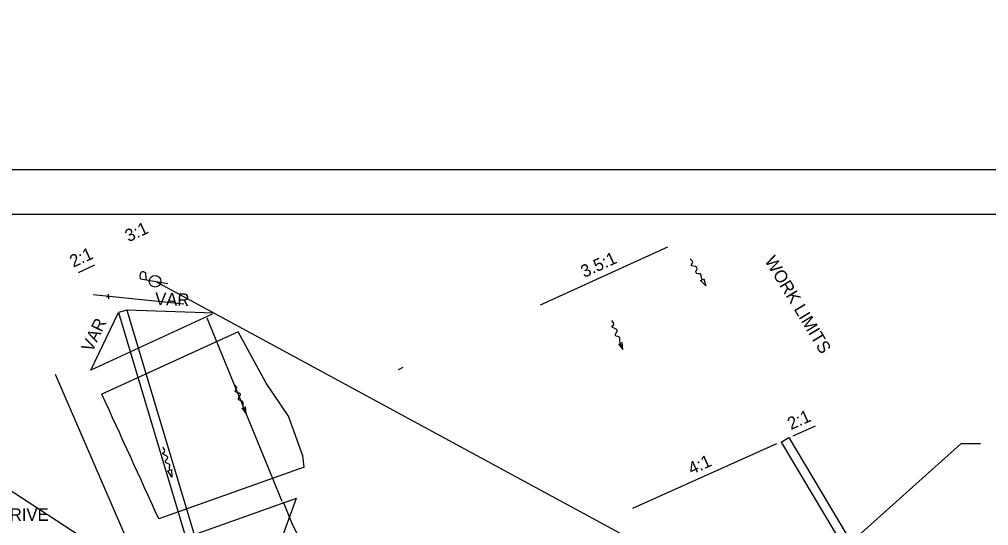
# Model space of a CAD drawing. Extents: x -1270 to 3371, y -118 to 220.
# Drawn here: x -1179.1 to -1070.2, y 76.8 to 133.7 of the extents above; entities that cross this region are included whole.
import ezdxf

# ---------------------------------------------------------------- set-up
doc = ezdxf.new("R2010")
doc.units = 0
for name, color, linetype in [('Default', 7, 'Continuous'), ('DR_X_Culvert', 7, 'Continuous'), ('GE_P_Alignment', 7, 'Continuous'), ('GE_P_Alignment_100_Distances', 7, 'Continuous'), ('GE_P_Alignment_100_Stations', 7, 'Continuous'), ('MT_P_Work_Area', 7, 'Continuous'), ('PF_P_Grade_Line', 7, 'Continuous'), ('TX_P_1', 7, 'Continuous'), ('TX_X_1', 7, 'Continuous')]:
    doc.layers.add(name, color=color, linetype=linetype)

msp = doc.modelspace()

# ---------------------------------------------------------------- linework, layer by layer
at = {"layer": 'Default'}
for p, q in [((-1120.54, 101.62), (-1106.25, 108.14)), ((-1172.47, 105.25), (-1170.63, 106.11)), ((-1165.48, 104.55), (-1165.52, 104.97)), ((-1165.48, 104.55), (-1162.43, 104)), ((-1164.83, 104.43), (-1164.88, 105.03)), ((-1164.66, 103.82), (-1164.66, 103.82)), ((-1164.66, 103.82), (-1164.66, 103.82)), ((-1164.66, 103.82), (-1164.66, 103.82)), ((-1163.85, 104.26), (-1083.18, 60.61)), ((-1163.85, 104.26), (-1163.85, 104.26)), ((-1160.63, 101.67), (-1170.81, 102.74)), ((-1169.3, 102.53), (-1168.8, 102.57)), ((-1169.03, 102.3), (-1169.07, 102.8)), ((-1169.05, 102.55), (-1169.05, 102.55)), ((-1171.08, 94.29), (-1167.97, 100.74)), ((-1157.44, 100.55), (-1171.08, 94.29)), ((-1157.2, 100.66), (-1167.01, 101.02)), ((-1158.05, 100.16), (-1149.6, 79.58)), ((-1154.52, 98.59), (-1169.82, 91.57)), ((-1166.15, 73.31), (-1175.04, 93.79)), ((-1089.69, 88), (-1092.19, 86.87)), ((-1110.19, 78.77), (-1094.01, 86.05)), ((-1147.09, 83.38), (-1163.43, 77.57)), ((-1148, 79.88), (-1162.42, 74.75)), ((-1148, 79.88), (-1156.01, 58.15))]:
    msp.add_line(p, q, dxfattribs=at)
for points in [[(-1147.09, 83.38), (-1147.24, 84.66), (-1148.87, 89.13), (-1151.38, 92.83), (-1154.52, 98.59)], [(-1149.47, 79.5), (-1148.52, 77.18), (-1145.9, 71.77), (-1143.88, 68.91), (-1143.36, 66.12), (-1142.76, 64.06), (-1140.56, 59.52), (-1140, 56.26), (-1138.98, 52.98), (-1139.13, 50.64)]]:
    msp.add_lwpolyline(points, dxfattribs=at)
msp.add_circle((-1163.85, 104.26), 0.65, dxfattribs=at)
for centre, radius, start, end in [((-1165.2, 105.01), 0.319, 3.6136, 185.8602), ((-5673.47, -1975.02), 4955.16, 24.47104, 24.64895)]:
    msp.add_arc(centre, radius, start, end, dxfattribs=at)
at = {"layer": 'DR_X_Culvert'}
msp.add_lwpolyline([(-1245.26, -103.22), (-905.26, -103.22), (-905.26, 116.78), (-1245.26, 116.78)], close=True, dxfattribs=at)
at = {"layer": 'GE_P_Alignment_100_Distances'}
for p, q in [((-1111.78, 97.25), (-1111.29, 96.58)), ((-1111.29, 96.58), (-1111.38, 97.41)), ((-1154.11, 90.06), (-1153.62, 89.39)), ((-1153.62, 89.39), (-1153.71, 90.21))]:
    msp.add_line(p, q, dxfattribs=at)
for points in [[(-1111.29, 96.58), (-1111.59, 97.36), (-1111.64, 97.7), (-1111.65, 97.92), (-1112.14, 98.18), (-1111.93, 98.78), (-1112.52, 99.15), (-1112.35, 99.34), (-1112.55, 99.85)], [(-1153.62, 89.39), (-1153.92, 90.16), (-1153.97, 90.5), (-1153.98, 90.72), (-1154.48, 90.98), (-1154.27, 91.58), (-1154.86, 91.95), (-1154.7, 92.14), (-1154.91, 92.64)]]:
    msp.add_spline(points, degree=3, dxfattribs=at)
at = {"layer": 'GE_P_Alignment_100_Stations'}
for p, q in [((-1102.57, 104.33), (-1102.2, 104.55)), ((-1102.2, 104.55), (-1101.99, 103.75)), ((-1101.99, 103.75), (-1102.57, 104.33)), ((-1162.4, 82.99), (-1161.99, 83.11)), ((-1161.96, 82.28), (-1162.4, 82.99)), ((-1161.99, 83.11), (-1161.96, 82.28))]:
    msp.add_line(p, q, dxfattribs=at)
for points in [[(-1102.39, 104.44), (-1102.4, 104.47), (-1102.5, 104.79), (-1102.55, 105.01), (-1103.08, 105.19), (-1102.97, 105.82), (-1103.61, 106.09), (-1103.47, 106.3), (-1103.75, 106.77)], [(-1162.19, 83.05), (-1162.2, 83.08), (-1162.22, 83.42), (-1162.21, 83.64), (-1162.69, 83.94), (-1162.43, 84.52), (-1162.99, 84.94), (-1162.81, 85.11), (-1162.97, 85.64)]]:
    msp.add_spline(points, degree=3, dxfattribs=at)
at = {"layer": 'MT_P_Work_Area'}
msp.add_line((-1136.01, 94.57), (-1136.55, 94.32), dxfattribs=at)
at = {"layer": 'PF_P_Grade_Line'}
for p, q in [((-1167.01, 101.02), (-1167.97, 100.74)), ((-1167.97, 100.74), (-1154.78, 56.67)), ((-1167.01, 101.02), (-1153.82, 56.95)), ((-1093.53, 86.21), (-1092.67, 86.72)), ((-1093.53, 86.21), (-1076.08, 57.03)), ((-1092.67, 86.72), (-1075.22, 57.54))]:
    msp.add_line(p, q, dxfattribs=at)
at = {"layer": 'TX_P_1'}
for p, q in [((-1261.12, 133.66), (-876.01, -117.63)), ((-1115.28, 48.52), (-1073.33, 85.99)), ((-1071.11, 85.99), (-1073.33, 85.99))]:
    msp.add_line(p, q, dxfattribs=at)
at = {"layer": 'TX_X_1'}
msp.add_lwpolyline([(-1230.26, 111.78), (-910.26, 111.78), (-910.26, -98.22), (-1230.26, -98.22)], close=True, dxfattribs=at)

# ---------------------------------------------------------------- texts
at = {"layer": 'GE_P_Alignment'}
msp.add_text('RESIDENTIAL DRIVE', height=1.4, dxfattribs=at).set_placement((-1194.32, 77.36))
at = {"layer": 'TX_P_1'}
for s, rotation, p in [('3:1', 24.8054, (-1166.83, 108.63)), ('2:1', 24.8054, (-1173.04, 105.77)), ('3.5:1', 24.5182, (-1115.64, 104.63)), ('WORK LIMITS', 301.1437, (-1095.42, 106.58)), ('VAR', 357.8847, (-1163.87, 101.61)), ('VAR', 64.2667, (-1170.93, 96.21)), ('VAR', 64.2667, (-1170.93, 96.21)), ('2:1', 24.231, (-1092.42, 87.54)), ('4:1', 24.231, (-1103.58, 82.51))]:
    msp.add_text(s, height=1.4, rotation=rotation, dxfattribs=at).set_placement(p)

doc.saveas('drawing.dxf')
